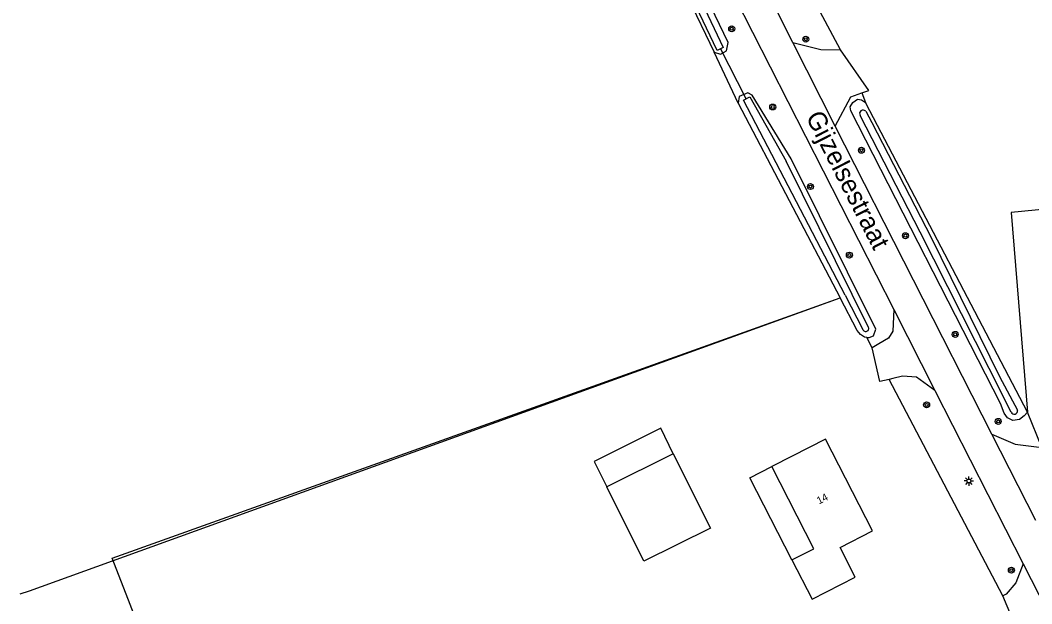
# Model space of a CAD drawing. Extents: x 140000 to 143000, y 403500 to 406000.
# Drawn here: x 141540.2 to 141675.8, y 404486.5 to 404564.8 of the extents above; entities that cross this region are included whole.
import ezdxf

# ---------------------------------------------------------------- set-up
doc = ezdxf.new("R2010")
doc.units = 0
for name, color, linetype in [('gg-afsc-erfafscheiding', 7, 'Continuous'), ('gg-afsc-hekwerk', 7, 'Continuous'), ('gg-anno-huisnummerreeks BGT', 7, 'Continuous'), ('gg-anno-openbare ruimte label', 7, 'Continuous'), ('gg-bbg-bijgebouw', 7, 'Continuous'), ('gg-bbg-hoofdgebouw', 7, 'Continuous'), ('gg-bbg-luifel en loopbrug', 7, 'Continuous'), ('gg-bbg-open loods', 7, 'Continuous'), ('gg-knt-bronhoudergrens', 7, 'Continuous'), ('gg-knt-verharding', 7, 'Continuous'), ('gg-knt-verharding nz', 7, 'Continuous'), ('gg-kntw-bovenkant insteek waterloop', 7, 'Continuous'), ('gg-kntw-waterlijn', 7, 'Continuous'), ('gg-kwrk-duiker nz buis', 7, 'Continuous'), ('gt-grn-groengrens', 7, 'Continuous'), ('gt-grn-vlakafsluiter', 7, 'Continuous'), ('gt-symb-boom', 7, 'Continuous'), ('gt-symb-lichtmast', 7, 'Continuous'), ('gx-grn-maaiveld', 7, 'Continuous')]:
    doc.layers.add(name, color=color, linetype=linetype)

# ---------------------------------------------------------------- blocks, each defined once
blk = doc.blocks.new('gt0-BOOM')
at = {"layer": 'gt-symb-boom'}
for radius in [0.4, 0.2]:
    blk.add_circle((0, 0), radius, dxfattribs=at)
blk = doc.blocks.new('gt0-LMAST')
at = {"layer": 'gt-symb-lichtmast'}
for p, q in [((-0.18, 0.17), (-0.45, 0.44)), ((-0.01, 0.25), (-0.01, 0.62)), ((0.17, 0.17), (0.44, 0.44)), ((-0.26, 0), (-0.63, 0)), ((-0.18, -0.18), (-0.45, -0.45)), ((-0.01, -0.25), (-0.01, -0.63)), ((0.44, -0.45), (0.17, -0.18)), ((0.24, 0), (0.62, 0))]:
    blk.add_line(p, q, dxfattribs=at)
blk.add_circle((-0.01, 0), 0.25, dxfattribs=at)

msp = doc.modelspace()

# ---------------------------------------------------------------- linework, layer by layer
at = {"layer": 'gg-afsc-erfafscheiding'}
for p, q in [((141654.38, 404520.84), (141653.64, 404522.23)), ((141671.87, 404487.59), (141656.62, 404516.59))]:
    msp.add_line(p, q, dxfattribs=at)
at = {"layer": 'gg-afsc-hekwerk'}
for p, q in [((141541.38, 404488.26), (141650.09, 404527.54)), ((141540.16, 404487.82), (141541.38, 404488.26))]:
    msp.add_line(p, q, dxfattribs=at)
at = {"layer": 'gg-bbg-bijgebouw'}
msp.add_line((141627.7, 404506.63), (141618.78, 404502.2), dxfattribs=at)
msp.add_lwpolyline([(141627.7, 404506.63), (141632.68, 404496.63), (141623.77, 404492.2), (141618.78, 404502.2)], dxfattribs=at)
at = {"layer": 'gg-bbg-hoofdgebouw'}
for points in [[(141643.6, 404492.39), (141646.3, 404487.11), (141652.07, 404490.07), (141650.05, 404494.04), (141654.41, 404496.27), (141648.1, 404508.59), (141643.65, 404506.3), (141640.89, 404504.9), (141640.89, 404504.9)], [(141643.6, 404492.39), (141646.53, 404493.89), (141640.89, 404504.9)]]:
    msp.add_lwpolyline(points, dxfattribs=at)
at = {"layer": 'gg-bbg-luifel en loopbrug'}
msp.add_lwpolyline([(141643.6, 404492.39), (141637.95, 404503.4), (141640.89, 404504.9)], dxfattribs=at)
at = {"layer": 'gg-bbg-open loods'}
msp.add_lwpolyline([(141627.7, 404506.63), (141626.01, 404510.03), (141617.09, 404505.59), (141618.78, 404502.2)], dxfattribs=at)
at = {"layer": 'gg-knt-bronhoudergrens'}
msp.add_line((141652.98, 404555.01), (141653.47, 404553.72), dxfattribs=at)
msp.add_lwpolyline([(141674.12, 404480.65), (141633.29, 404465.24), (141603.32, 404461.36), (141581.14, 404457.47), (141568.76, 404454.69), (141565.18, 404459.93), (141552.48, 404492.63), (141650.09, 404527.54)], dxfattribs=at)
at = {"layer": 'gg-knt-verharding'}
for p, q in [((141627.4, 404584.68), (141657.25, 404525.95)), ((141643.73, 404561.76), (141636.68, 404575.71)), ((141670.42, 404509.26), (141649.4, 404550.57)), ((141662.77, 404515.1), (141674.58, 404491.88)), ((141673.98, 404482.63), (141671.87, 404487.59))]:
    msp.add_line(p, q, dxfattribs=at)
for points in [[(141643.73, 404561.76), (141647.46, 404560.81), (141650.13, 404560.79)], [(141652.98, 404555.01), (141653.89, 404555.32), (141650.13, 404560.79)], [(141649.4, 404550.57), (141651.5, 404554.5), (141652.98, 404555.01)], [(141657.25, 404525.95), (141657.15, 404523.07), (141656.55, 404522.1), (141655.27, 404521.36), (141654.38, 404520.84)], [(141656.62, 404516.59), (141655.38, 404516.29), (141654.38, 404520.84)], [(141662.77, 404515.1), (141660.3, 404516.88), (141658.44, 404517.02), (141657.14, 404516.71), (141656.62, 404516.59)], [(141670.42, 404509.26), (141673.53, 404507.91), (141677.12, 404507.47)], [(141674.58, 404491.88), (141673.62, 404489.29), (141672.31, 404487.81), (141671.87, 404487.59)]]:
    msp.add_lwpolyline(points, dxfattribs=at)
at = {"layer": 'gg-knt-verharding nz'}
for p, q in [((141649.4, 404550.57), (141643.73, 404561.76)), ((141657.25, 404525.95), (141662.77, 404515.1)), ((141676.32, 404497.66), (141670.42, 404509.26)), ((141674.58, 404491.88), (141679.62, 404481.96))]:
    msp.add_line(p, q, dxfattribs=at)
at = {"layer": 'gg-kntw-bovenkant insteek waterloop'}
for p, q in [((141623.12, 404581.47), (141633.16, 404560.49)), ((141636.38, 404553.65), (141650.09, 404527.54))]:
    msp.add_line(p, q, dxfattribs=at)
for points in [[(141633.16, 404560.49), (141634.02, 404560.22), (141634.82, 404560.67), (141635.07, 404561.76), (141625.65, 404581.29)], [(141643.48, 404546.17), (141638.27, 404554.71), (141637.69, 404555.04), (141636.53, 404554.55), (141636.38, 404553.65)], [(141675.19, 404512.2), (141674.75, 404511.72), (141674.1, 404511.21), (141673.23, 404511.09), (141672.52, 404511.46), (141672.07, 404512.05), (141671.54, 404513.36), (141651.51, 404552.61), (141651.4, 404553.13), (141651.78, 404553.72), (141652.37, 404554.16), (141652.94, 404554.1), (141653.47, 404553.72)], [(141675.19, 404512.2), (141654.03, 404552.62), (141653.47, 404553.72)], [(141653.64, 404522.23), (141653.94, 404522.21), (141654.54, 404522.42), (141654.84, 404523.31), (141643.48, 404546.17)], [(141653.64, 404522.23), (141653.33, 404522.25), (141652.8, 404522.62), (141652.36, 404523.15), (141650.09, 404527.54)]]:
    msp.add_lwpolyline(points, dxfattribs=at)
at = {"layer": 'gg-kntw-waterlijn'}
for p, q in [((141653.87, 404523.57), (141642.81, 404545.84)), ((141650.76, 404527.88), (141653.12, 404523.29))]:
    msp.add_line(p, q, dxfattribs=at)
for points in [[(141624.99, 404580.93), (141634.39, 404561.12), (141633.58, 404560.68), (141623.19, 404582.54)], [(141650.76, 404527.88), (141637.1, 404554.02), (141637.97, 404554.47), (141642.81, 404545.84)], [(141653.49, 404552.56), (141654.3, 404551.03), (141662.28, 404535.63), (141671.43, 404516.99), (141673.85, 404512.46)], [(141672.98, 404512.18), (141670.05, 404518.05), (141660.79, 404536.35), (141652.76, 404551.98)]]:
    msp.add_lwpolyline(points, dxfattribs=at)
for centre, radius, start, end in [((141653.14, 404552.25), 0.465, 41.6018, 215.1009), ((141653.5, 404523.42), 0.402, 199.7004, 22.3131), ((141673.39, 404512.39), 0.46, 206.5599, 8.6366)]:
    msp.add_arc(centre, radius, start, end, dxfattribs=at)
at = {"layer": 'gg-kwrk-duiker nz buis'}
msp.add_line((141633.99, 404560.99), (141637.42, 404554.24), dxfattribs=at)
at = {"layer": 'gt-grn-groengrens'}
for p, q in [((141650.13, 404560.79), (141640.18, 404579.28)), ((141677.12, 404507.47), (141675.19, 404512.2))]:
    msp.add_line(p, q, dxfattribs=at)
at = {"layer": 'gt-grn-vlakafsluiter'}
msp.add_line((141636.38, 404553.65), (141633.16, 404560.49), dxfattribs=at)
at = {"layer": 'gx-grn-maaiveld'}
msp.add_lwpolyline([(141741.09, 404550.9), (141714.9, 404545.43), (141715.52, 404542.18), (141690.73, 404529.24), (141686.32, 404540.27), (141672.97, 404538.97), (141675.19, 404512.2)], dxfattribs=at)

# ---------------------------------------------------------------- block references
at = {"layer": 'gt-symb-boom'}
for p in [(141635.53, 404563.61), (141645.46, 404562.21), (141641.03, 404553.12), (141652.92, 404547.32), (141646.09, 404542.45), (141658.82, 404535.86), (141651.3, 404533.26), (141665.49, 404522.63), (141661.66, 404513.18), (141671.25, 404510.96), (141673.02, 404491.01)]:
    msp.add_blockref('gt0-BOOM', p, dxfattribs=at)
at = {"layer": 'gt-symb-lichtmast'}
msp.add_blockref('gt0-LMAST', (141667.33, 404502.97), dxfattribs=at)

# ---------------------------------------------------------------- texts
at = {"layer": 'gg-anno-huisnummerreeks BGT'}
msp.add_text('14', height=1, rotation=27.1, dxfattribs=at).set_placement((141647.23, 404499.81))
at = {"layer": 'gg-anno-openbare ruimte label'}
msp.add_text('Gijzelsestraat', height=2.5, rotation=297, dxfattribs=at).set_placement((141645.41, 404551.81))

doc.saveas('drawing.dxf')
